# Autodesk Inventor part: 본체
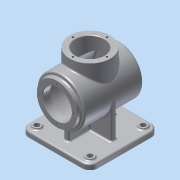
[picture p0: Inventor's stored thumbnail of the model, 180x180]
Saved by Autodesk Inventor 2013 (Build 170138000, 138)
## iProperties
Created: 2015-07
Part Number: 본체
Material: 알루미늄 6061
Document SubType Name: Modeling
Designer: dgall
Density: 2.71 g/cm^3
Mass: 1277.48 g
Surface Area: 1268.17 cm^2
Volume: 471.394 cm^3
Author: dgall
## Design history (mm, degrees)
sketch "스케치1"
  geometry: L1 (-65, 65)-(65, 65); L2 (65, 65)-(65, -65); L3 (65, -65)-(-65, -65); L4 (-65, -65)-(-65, 65); 3 further points
  constraints: 8 end point, 2 midpoint, 2 parallel, 2 perpendicular, 1 horizontal, 1 horizontal alignment, 1 vertical alignment
  dimensions: "d0" = 130 distance of L1.start L1.end
extrude "돌출1" new body sketch "스케치1" distance "d3" = 10; taper "d4" = 0 deg
sketch "스케치2"
  geometry: L1 (68, 55)-(68, -55); L2 (-10, 65)-(-10, -65) reference; L3 (68, 55)-(113, 55); L4 (113, 55)-(113, -55); L5 (113, -55)-(68, -55); 2 further points
  constraints: 8 end point, 2 perpendicular, 1 horizontal alignment, 1 midpoint, 1 parallel, 1 vertical
  dimensions: "d5" = 78 distance between parallel lines of L2 L1; "d6" = 110 distance of L1.start L1.end; "d7" = 90 diameter of L4 L1
revolve "회전1" sketch "스케치2" stored, may be unused: angle "d8" = 90 deg
sketch "스케치3"
  geometry: C1 r 45 at (0, 0) reference; C2 r 38 at (0, 0); 1 further point
  constraints: 1 centre point, 1 coincident
  dimensions: "d9" = 76 diameter of C2
extrude "돌출2" join sketch "스케치3" distance "d11" = 7; taper "d12" = 0 deg
node "작업 평면1"
sketch "스케치5"
  geometry: C1 r 38 at (0, 0); 1 further point
  constraints: 1 centre point, 1 coincident
  dimensions: "d14" = 76 diameter of C1
extrude "돌출3" join sketch "스케치5" distance "d16" = 62; taper "d17" = 0 deg
sketch "스케치7"
  geometry: L1 (-5, 45)-(5, 45); L2 (5, -45)-(-5, -45); L3 (45, 5)-(45, -5); L4 (-45, -5)-(-45, 5); L5 (5, 45)-(5, 5); L6 (5, -5)-(5, -45); L7 (-45, 5)-(-5, 5); L8 (5, 5)-(45, 5); L9 (-5, -45)-(-5, -5); L10 (-5, 5)-(-5, 45); L11 (45, -5)-(5, -5); L12 (-5, -5)-(-45, -5); 4 further points
  constraints: 24 end point, 14 parallel, 4 perpendicular, 3 horizontal, 3 midpoint, 2 vertical alignment, 1 horizontal alignment
  dimensions: "d18" = 10 distance of L1.start L1.end; "d20" = 10 distance of L4.start L4.end; "d21" = 90 distance between parallel lines of L3 L4; "d23" = 45 distance from line of point (0, 0) L1; "d24" = 45 distance from line of L2 point (0, 0)
extrude "돌출4" join sketch "스케치7" stored distance "d25" = 62; taper "d26" = 0 deg
sketch "스케치8"
  geometry: L1 (106, 62)-(30, 62) reference; L2 (23, -55)-(113, -55) reference; L3 (68, 62)-(68, -55); L4 (68, 62)-(95, 62); L5 (95, 62)-(95, 48); L6 (95, 48)-(108, 48); L7 (108, 48)-(108, -48); L8 (108, -48)-(68, -48); 1 further point
  constraints: 12 end point, 3 perpendicular, 2 midpoint, 2 point on line, 1 parallel
  dimensions: "d27" = 54 diameter of L5 L3; "d29" = 14 distance of L4.end L5.end; "d30" = 96 distance between parallel lines of L8 L6; "d31" = 80 diameter of L7 L3
revolve "회전2" sketch "스케치8" stored, may be unused: angle "d32" = 90 deg
sketch "스케치9"
  geometry: C1 r 38 at (0, 0) reference; C2 r 27 at (0, 0)
  constraints: 1 centre point, 1 coincident
  dimensions: "d33" = 54 diameter of C2
extrude "돌출5" cut sketch "스케치9" stored distance "d35" = 62; taper "d36" = 0 deg
fillet "모깎기6" dims "d39" = 15
sketch "스케치10"
  geometry: C1 r 7.5 at (-50, 50); C2 r 5 at (-50, 50); A1 r 15 centre (-50, 50) between (-50, 65) and (-65, 50) reference; 1 further point
  constraints: 2 centre point, 2 coincident
  dimensions: "d41" = 15 diameter of C1; "d43" = 10 diameter of C2
extrude "돌출6" join sketch "스케치10" distance "d44" = 13; taper "d45" = 0 deg
extrude "돌출7" cut sketch "스케치10" distance "d46" = 13; taper "d47" = 0 deg
sketch "스케치11"
  geometry: C1 r 27 at (0, 0) reference; 1 further point
  constraints: 1 vertical alignment
  dimensions: "d54" = 32 distance of C1.centre point (0, 32)
hole "구멍1" sketch "스케치11" at (0, 32) diameter "d55" = 3.459; stored, may be unused: countersink angle "d59" = 90 deg, drill point angle "d61" = 118 deg; dims "d56" = 8, "d57" = 4, "d58" = 2, "d60" = 10
sketch "스케치12"
  geometry: C1 r 27 at (0, 0) reference; 2 further points
  constraints: 1 vertical alignment
  dimensions: "d65" = 32 distance of C1.centre point (0, 32)
hole "구멍2" sketch "스케치12" at (0, 32) diameter "d66" = 3.459; stored, may be unused: countersink angle "d70" = 90 deg, drill point angle "d72" = 118 deg; dims "d67" = 8, "d68" = 4, "d69" = 2, "d71" = 10
fillet "모깎기10" dims "d78" = 3
fillet "모깎기11" dims "d79" = 3
fillet "모깎기12" dims "d80" = 3
chamfer "모따기1" distance "d81" = 1; stored, may be unused: second distance "d82" = 2, angle "d83" = 45 deg
fillet "모깎기13" dims "d84" = 3
sketch "스케치13"
  geometry: C1 r 42 at (0, 0) reference; 2 further points
  constraints: 1 coincident, 1 other
feature "엠보싱1" sketch "스케치13" dims "d0" = 130, "d85" = 0.5, "d86" = 0
node "솔리드1"
pattern_linear "직사각형 패턴1"
pattern_circular "원형 패턴1" dims angle "d63" = 360 deg
pattern_circular "원형 패턴2" dims angle "d74" = 360 deg
other parameters: "d13" = 68
